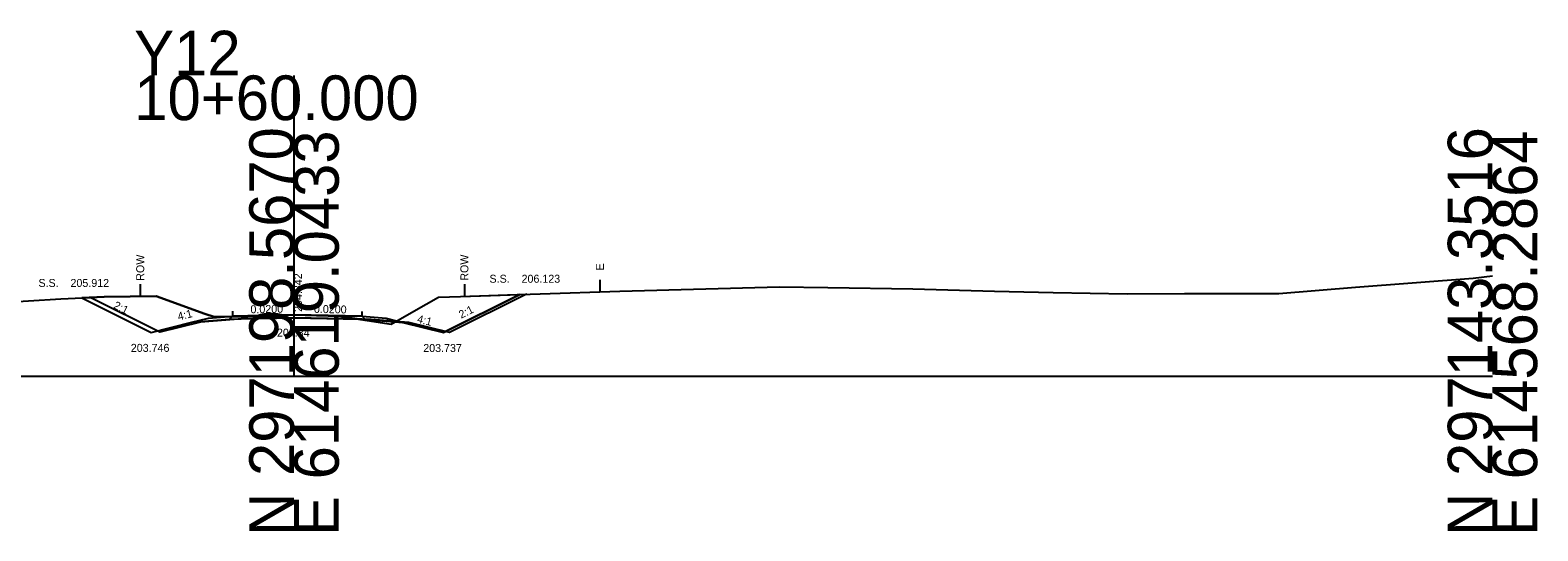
# Model space of a CAD drawing. Extents: x 517327 to 517505, y 114839 to 117367.
# Drawn here: x 517410.9 to 517505.2, y 116338.7 to 116370.1 of the extents above; entities that cross this region are included whole.
import ezdxf

# ---------------------------------------------------------------- set-up
doc = ezdxf.new("R2010")
doc.units = 0
for name, color, linetype in [('Exist XS Ground Line', 7, 'Continuous'), ('Old_Level_3', 7, 'Continuous'), ('Old_Level_5', 7, 'Continuous'), ('Old_Level_59', 7, 'Continuous'), ('Old_Level_63', 7, 'Continuous'), ('Prop XS Dump Level', 7, 'Continuous'), ('Prop XS Earthwork Shape', 7, 'Continuous'), ('Prop XS Elevation Labels', 7, 'Continuous'), ('Prop XS EOT Tick Mark', 7, 'Continuous'), ('Prop XS Exc Vertical Line 1', 7, 'Continuous'), ('Prop XS Exc Vertical Line 2', 7, 'Continuous'), ('Prop XS Finish Grade', 7, 'Continuous'), ('Prop XS Finish Grade Earthwork', 7, 'Continuous'), ('Prop XS Finish Grade Pavement', 7, 'Continuous'), ('Prop XS Hydro Elevations', 7, 'Continuous'), ('Prop XS Pvmt Edge Slope', 7, 'Continuous'), ('Prop XS Side Slope Text', 7, 'Continuous'), ('Prop XS Subgrade Earthwork', 7, 'Continuous'), ('Prop XS Suitable Common Exc Shape', 7, 'Continuous')]:
    doc.layers.add(name, color=color, linetype=linetype)

msp = doc.modelspace()

# ---------------------------------------------------------------- linework, layer by layer
at = {"layer": 'Exist XS Ground Line'}
for p, q in [((517447.746, 116353.691), (517457.737, 116353.96)), ((517457.737, 116353.96), (517460.772, 116353.923)), ((517460.772, 116353.923), (517466.085, 116353.842)), ((517466.085, 116353.842), (517471.204, 116353.7)), ((517489.002, 116353.544), (517493.785, 116353.948)), ((517493.785, 116353.948), (517501.154, 116354.518)), ((517501.154, 116354.518), (517502.365, 116354.647)), ((517408.212, 116352.933), (517412.767, 116353.221)), ((517412.767, 116353.221), (517415.473, 116353.335)), ((517415.473, 116353.335), (517418.727, 116353.389)), ((517418.727, 116353.389), (517421.787, 116352.278)), ((517433.442, 116351.634), (517435.636, 116352.87)), ((517435.636, 116352.87), (517436.41, 116353.311)), ((517436.41, 116353.311), (517437.781, 116353.367)), ((517437.781, 116353.367), (517447.746, 116353.691)), ((517471.204, 116353.7), (517474.863, 116353.619)), ((517474.863, 116353.619), (517479.512, 116353.523)), ((517479.512, 116353.523), (517483.082, 116353.541)), ((517483.082, 116353.541), (517489.002, 116353.544)), ((517421.787, 116352.278), (517422.37, 116352.078)), ((517422.37, 116352.078), (517423.681, 116352.097)), ((517423.681, 116352.097), (517424.48, 116352.108)), ((517424.48, 116352.108), (517427.338, 116352.202)), ((517427.338, 116352.202), (517430.203, 116352.128)), ((517430.203, 116352.128), (517430.715, 116352.05)), ((517430.715, 116352.05), (517433.442, 116351.634))]:
    msp.add_line(p, q, dxfattribs=at)
at = {"layer": 'Old_Level_63'}
for p, q in [((517427.365, 116348.365), (517427.365, 116367.211)), ((517352.365, 116348.365), (517427.365, 116348.365)), ((517427.365, 116348.365), (517502.365, 116348.365))]:
    msp.add_line(p, q, dxfattribs=at)
at = {"layer": 'Prop XS Dump Level'}
for p, q in [((517423.516, 116352.13), (517427.365, 116352.207)), ((517427.365, 116352.207), (517431.624, 116352.122))]:
    msp.add_line(p, q, dxfattribs=at)
at = {"layer": 'Prop XS Earthwork Shape'}
for points in [[(517414.083, 116353.276), (517418.416, 116351.11), (517420.967, 116351.748), (517422.016, 116351.832), (517423.322, 116351.936), (517424.065, 116351.951), (517427.365, 116352.017), (517431.47, 116351.935), (517430.715, 116352.05), (517430.203, 116352.128), (517427.338, 116352.202), (517424.48, 116352.108), (517423.681, 116352.097), (517422.37, 116352.078), (517421.787, 116352.278), (517418.727, 116353.389), (517415.473, 116353.335)], [(517433.697, 116351.778), (517435.636, 116352.87), (517436.41, 116353.311), (517437.781, 116353.367), (517441.496, 116353.488), (517436.724, 116351.102), (517434.173, 116351.74)], [(517431.624, 116351.932), (517431.47, 116351.935), (517433.442, 116351.634), (517433.697, 116351.778), (517433.124, 116351.824), (517431.818, 116351.928)]]:
    msp.add_lwpolyline(points, close=True, dxfattribs=at)
at = {"layer": 'Prop XS EOT Tick Mark'}
for p, q in [((517423.516, 116352.435), (517423.516, 116352.13)), ((517431.624, 116352.122), (517431.624, 116352.427))]:
    msp.add_line(p, q, dxfattribs=at)
at = {"layer": 'Prop XS Exc Vertical Line 1'}
msp.add_line((517446.506, 116354.401), (517446.506, 116353.651), dxfattribs=at)
at = {"layer": 'Prop XS Exc Vertical Line 2'}
for p, q in [((517417.739, 116354.122), (517417.739, 116353.372)), ((517438.026, 116354.125), (517438.026, 116353.375))]:
    msp.add_line(p, q, dxfattribs=at)
at = {"layer": 'Prop XS Finish Grade'}
for p, q in [((517420.967, 116351.748), (517422.016, 116352.01)), ((517422.016, 116352.01), (517423.516, 116352.13)), ((517431.624, 116352.122), (517433.124, 116352.002)), ((517433.124, 116352.002), (517434.173, 116351.74))]:
    msp.add_line(p, q, dxfattribs=at)
at = {"layer": 'Prop XS Finish Grade Earthwork'}
for p, q in [((517414.083, 116353.276), (517418.416, 116351.11)), ((517436.724, 116351.102), (517441.496, 116353.488)), ((517418.416, 116351.11), (517420.967, 116351.748)), ((517434.173, 116351.74), (517436.724, 116351.102))]:
    msp.add_line(p, q, dxfattribs=at)
at = {"layer": 'Prop XS Finish Grade Pavement'}
for p, q in [((517427.365, 116352.207), (517423.516, 116352.13)), ((517431.624, 116352.122), (517427.365, 116352.207))]:
    msp.add_line(p, q, dxfattribs=at)
at = {"layer": 'Prop XS Pvmt Edge Slope'}
for p, q in [((517423.322, 116351.936), (517423.516, 116352.13)), ((517431.624, 116352.122), (517431.818, 116351.928))]:
    msp.add_line(p, q, dxfattribs=at)
at = {"layer": 'Prop XS Subgrade Earthwork'}
for p, q in [((517422.016, 116351.832), (517423.322, 116351.936)), ((517423.322, 116351.936), (517424.065, 116351.951)), ((517427.365, 116352.017), (517424.065, 116351.951)), ((517431.624, 116351.932), (517427.365, 116352.017)), ((517431.624, 116351.932), (517431.818, 116351.928)), ((517431.818, 116351.928), (517433.124, 116351.824)), ((517420.967, 116351.748), (517422.016, 116351.832)), ((517433.124, 116351.824), (517434.173, 116351.74))]:
    msp.add_line(p, q, dxfattribs=at)
at = {"layer": 'Prop XS Suitable Common Exc Shape'}
for points in [[(517431.47, 116351.935), (517427.365, 116352.017), (517424.065, 116351.951), (517423.871, 116351.947), (517422.565, 116351.843), (517421.516, 116351.759), (517418.965, 116351.121), (517414.61, 116353.299), (517415.473, 116353.335), (517418.727, 116353.389), (517421.787, 116352.278), (517422.37, 116352.078), (517423.681, 116352.097), (517424.48, 116352.108), (517427.338, 116352.202), (517430.203, 116352.128), (517430.715, 116352.05)], [(517437.781, 116353.367), (517441.905, 116353.501), (517437.092, 116351.095), (517434.541, 116351.732), (517433.731, 116351.797), (517435.636, 116352.87), (517436.41, 116353.311)], [(517433.442, 116351.634), (517433.731, 116351.797), (517433.492, 116351.816), (517432.186, 116351.921), (517431.992, 116351.925), (517431.47, 116351.935)]]:
    msp.add_lwpolyline(points, close=True, dxfattribs=at)

# ---------------------------------------------------------------- texts
at = {"layer": 'Old_Level_3'}
for rotation, p in [(14.03624, (517420.143, 116351.851)), (345.96376, (517435.029, 116351.735))]:
    msp.add_text('4:1', height=0.5, rotation=rotation, dxfattribs=at).set_placement(p)
at = {"layer": 'Old_Level_5'}
for rotation, p in [(1.14576, (517424.642, 116352.305)), (358.85423, (517428.606, 116352.335))]:
    msp.add_text('0.0200', height=0.5, rotation=rotation, dxfattribs=at).set_placement(p)
at = {"layer": 'Old_Level_59'}
msp.add_text(' 204.842', height=0.5, rotation=90, dxfattribs=at).set_placement((517427.865, 116352.207))
msp.add_text(' 204.842', height=0.5, rotation=90, dxfattribs=at).set_placement((517427.865, 116352.207))
msp.add_text(' 204.842', height=0.5, rotation=90, dxfattribs=at).set_placement((517427.865, 116352.207))
msp.add_text('204.84', height=0.5, dxfattribs=at).set_placement((517426.295, 116350.841))
at = {"layer": 'Old_Level_63'}
for s, p in [('Y12', (517417.362, 116367.211)), ('10+60.000', (517417.365, 116364.411))]:
    msp.add_text(s, height=2.8, dxfattribs=at).set_placement(p)
for s, p in [('N 297198.5670', (517427.365, 116338.364)), ('E 614619.0433', (517430.165, 116338.364)), ('N 297143.3516', (517502.365, 116338.364)), ('E 614568.2864', (517505.165, 116338.365))]:
    msp.add_text(s, height=2.8, rotation=90, dxfattribs=at).set_placement(p)
at = {"layer": 'Prop XS Elevation Labels'}
for p in [(517422.016, 116351.998), (517433.124, 116351.99)]:
    msp.add_text('Case1', height=0.0122, dxfattribs=at).set_placement(p)
at = {"layer": 'Prop XS Exc Vertical Line 1'}
msp.add_text('E', height=0.5, rotation=90, dxfattribs=at).set_placement((517446.756, 116354.993))
at = {"layer": 'Prop XS Exc Vertical Line 2'}
for p in [(517417.989, 116354.347), (517438.276, 116354.35)]:
    msp.add_text('ROW', height=0.5, rotation=90, dxfattribs=at).set_placement(p)
at = {"layer": 'Prop XS Hydro Elevations'}
for s, p in [('S.S.    205.912', (517411.368, 116353.958)), ('S.S.    206.123', (517439.597, 116354.222))]:
    msp.add_text(s, height=0.5, dxfattribs=at).set_placement(p)
at = {"layer": 'Prop XS Side Slope Text'}
for rotation, p in [(333.43495, (517416.018, 116352.644)), (26.56505, (517437.826, 116351.962))]:
    msp.add_text('2:1', height=0.5, rotation=rotation, dxfattribs=at).set_placement(p)
for s, p in [('203.746', (517417.15, 116349.89)), ('203.737', (517435.451, 116349.882))]:
    msp.add_text(s, height=0.5, dxfattribs=at).set_placement(p)

doc.saveas('drawing.dxf')
